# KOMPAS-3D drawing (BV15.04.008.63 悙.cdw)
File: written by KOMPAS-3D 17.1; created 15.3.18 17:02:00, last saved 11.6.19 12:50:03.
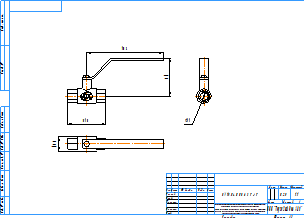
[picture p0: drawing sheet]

Sheet 1: A3, landscape

Title block, sheet 1: name: BV15.04.008.63 Р/Р; material: Внимание! Данный продукт является объектом авторского права ООО «Торговый Дом АДЛ». / Запрещается изменение, копирование, распространение / (в том числе путем копирования на другие сайты и ресурсы в Интернете) / или любое иное использование информации и объектов без предварительного / согласия правообладателя (ООО «Торговый Дом АДЛ»).; mass: 0,25; sheets: 1; organisation: ООО "Торговый дом АДЛ"; sheet format: A3; stored path: \\adlc.lan\data\АДЛ_ПКД\3D-модели\ADL production\Краны шаровые серии BV\BV15\KOMPAS 2D\BV15.04.008.63 РР.cdw

Views: Вид 1, Проекционный вид 2, Проекционный вид 3
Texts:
  kka
  adl
Dimensions and other numbers on the sheet: 51,5; 103; 51; 11; 19,8; 1:1; 1; 0,25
